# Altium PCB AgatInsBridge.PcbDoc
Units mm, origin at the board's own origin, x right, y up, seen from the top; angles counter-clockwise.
Board outline 85 x 24.01 mm, 2 copper layers (Top Layer, Bottom Layer); 85 components, 54 nets, 150 pads, 49 vias.
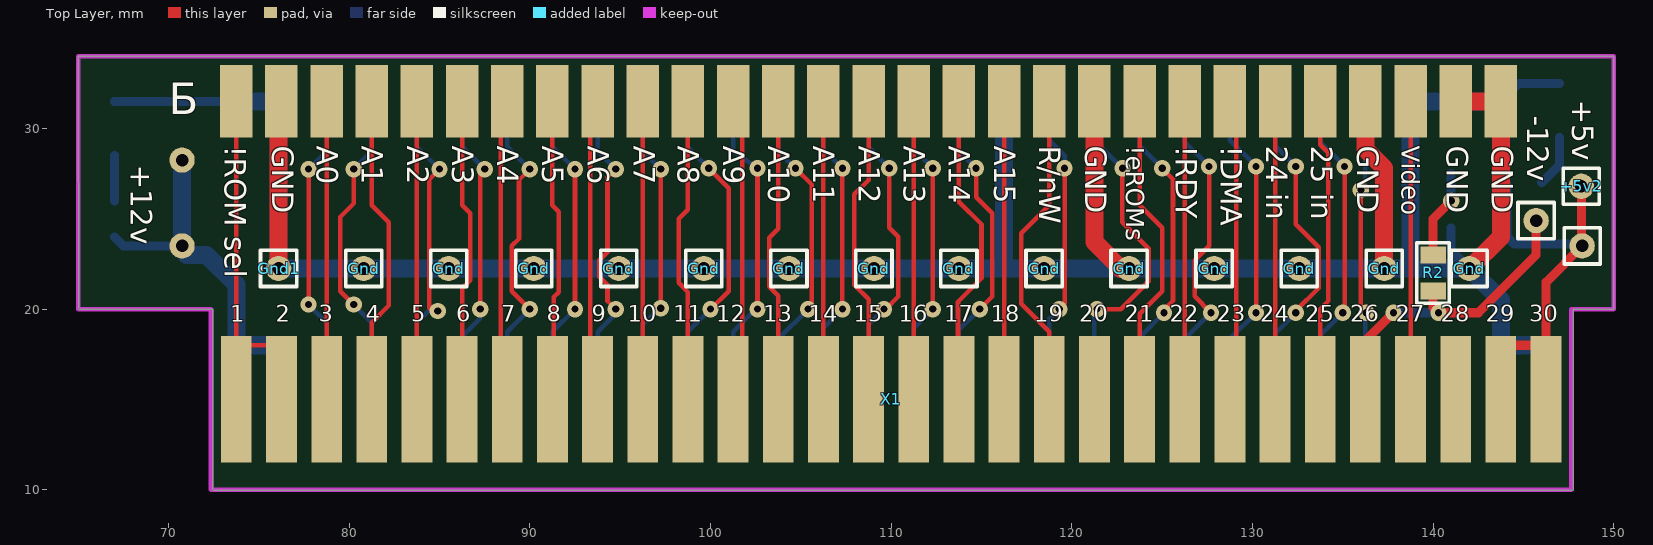
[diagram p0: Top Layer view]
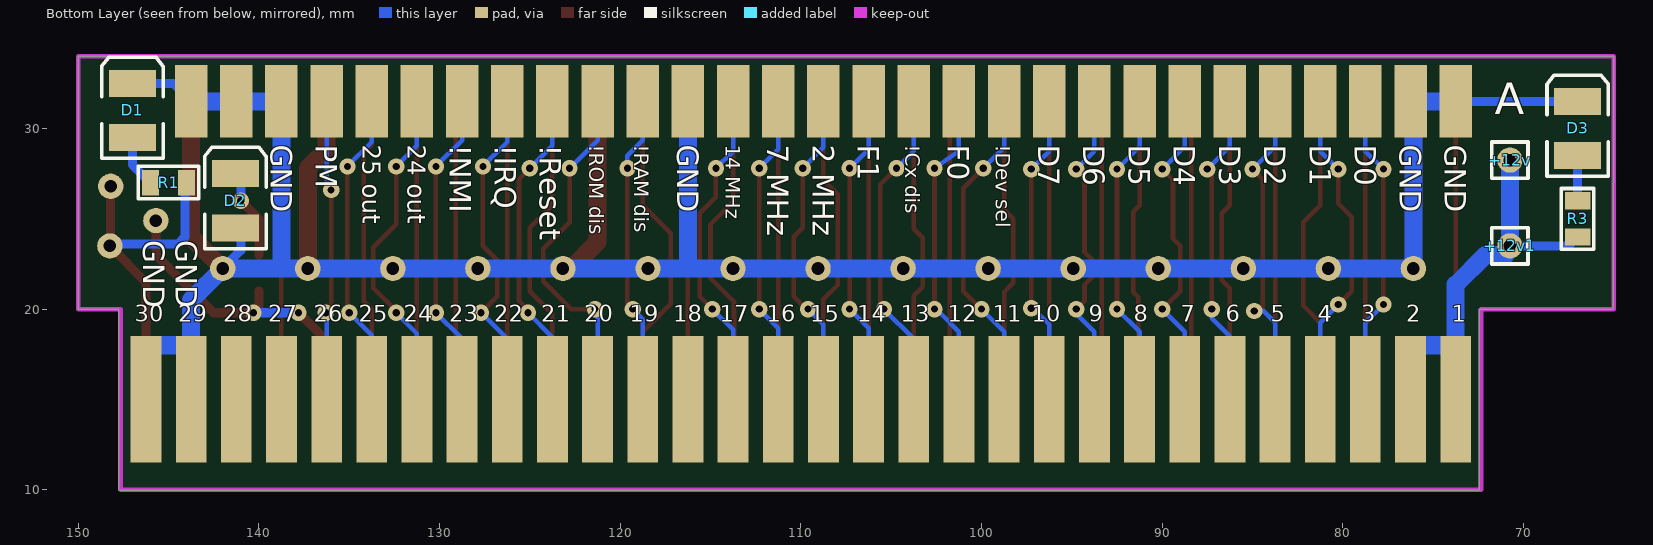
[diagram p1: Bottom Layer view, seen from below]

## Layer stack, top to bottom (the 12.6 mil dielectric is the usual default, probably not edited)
Top Solder: solder mask 0.0102, Solder Resist, Dk 3.5
Top Layer: signal copper 0.0356
Dielectric 1: dielectric 0.32, FR-4, Dk 4.8
Bottom Layer: signal copper 0.0356
Bottom Solder: solder mask 0.0102, Solder Resist, Dk 3.5

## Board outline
65.024,20 72.459,20 72.459,9.986 147.759,9.986 147.759,20 150,20 150,34 65,34

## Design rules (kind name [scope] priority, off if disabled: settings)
Clearance [All] p1: gap=0.254
PolygonConnect [All] p1: connectstyle=Relief reliefconductorwidth=0.254 reliefentries=4 polygonreliefangle="90 Angle" airgapwidth=0.254
RoutingVias [All] p1: holewidth=0.4 width=0.9 viastyle="Through Hole" minholewidth=0.4 minwidth=0.9 maxholewidth=0.4 maxwidth=0.9
SolderMaskExpansion [All] p1: expansion=0.102
Width [All] p1: maxlimit=1 minlimit=0.254 preferedwidth=0.5
30 further rules are at their usual default settings.

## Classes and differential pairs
component class AgatInsBridge: "2 MHz" "7 MHz" "14 MHz" "24 in" "24 out" "25 in" "25 out" "!Cx dis" "!Dev sel" !DMA !eROMs !IRQ !NMI "!RAM dis" !RDY !Reset "!ROM dis" "!ROM sel" +5v +5v2 +12v +12v1 +12v2 -12v A0 A1 A2 A3 A4 A5 A6 A7 A8 A9 A10 A11 A12 A13 A14 A15 D0 D1 D2 D3 D4 D5 D6 D7 F0 F1 Gnd GND PM R1 R2 R3 R/nW Video X1

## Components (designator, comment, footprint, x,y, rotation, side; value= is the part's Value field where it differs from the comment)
"2 MHz" "Wire pad" "Wire/Stick pad" 108.75,31.5 r180 bottom
"7 MHz" "Wire pad" "Wire/Stick pad" 111.25,31.5 r180 bottom
"14 MHz" "Wire pad" "Wire/Stick pad" 113.75,31.5 r180 bottom
"24 in" "Wire pad" "Wire/Stick pad" 131.25,31.5 r0 top
"24 out" "Wire pad" "Wire/Stick pad" 131.25,31.5 r180 bottom
"25 in" "Wire pad" "Wire/Stick pad" 133.75,31.5 r0 top
"25 out" "Wire pad" "Wire/Stick pad" 133.75,31.5 r180 bottom
"!Cx dis" "Wire pad" "Wire/Stick pad" 103.75,31.5 r180 bottom (schematic designator "!Cxxx dis")
"!Dev sel" "Wire pad" "Wire/Stick pad" 98.75,31.5 r180 bottom
!DMA "Wire pad" "Wire/Stick pad" 128.75,31.5 r0 top
!eROMs "Wire pad" "Wire/Stick pad" 123.75,31.5 r0 top (schematic designator "!eROM sel")
!IRQ "Wire pad" "Wire/Stick pad" 126.25,31.5 r180 bottom
!NMI "Wire pad" "Wire/Stick pad" 128.75,31.5 r180 bottom
"!RAM dis" "Wire pad" "Wire/Stick pad" 118.75,31.5 r180 bottom
!RDY "Wire pad" "Wire/Stick pad" 126.25,31.5 r0 top
!Reset "Wire pad" "Wire/Stick pad" 123.75,31.5 r180 bottom
"!ROM dis" "Wire pad" "Wire/Stick pad" 121.25,31.5 r180 bottom
"!ROM sel" "Wire pad" "Wire/Stick pad" 73.75,31.5 r0 top
+5v "Wire hole" "Wire hole" 148.25,23.5 r0 top (schematic designator +5v1)
+5v2 "Wire hole" "Wire hole" 148.2,26.8 r0 top
+12v "Wire hole" "Wire hole" 70.75,28.25 r180 bottom (schematic designator +12v2)
+12v1 "Wire hole" "Wire hole" 70.75,23.5 r180 bottom
-12v "Wire hole" "Wire hole" 145.7,24.9 r0 top
A0 "Wire pad" "Wire/Stick pad" 78.75,31.5 r0 top
A1 "Wire pad" "Wire/Stick pad" 81.25,31.5 r0 top
A2 "Wire pad" "Wire/Stick pad" 83.75,31.5 r0 top
A3 "Wire pad" "Wire/Stick pad" 86.25,31.5 r0 top
A4 "Wire pad" "Wire/Stick pad" 88.75,31.5 r0 top
A5 "Wire pad" "Wire/Stick pad" 91.25,31.5 r0 top
A6 "Wire pad" "Wire/Stick pad" 93.75,31.5 r0 top
A7 "Wire pad" "Wire/Stick pad" 96.25,31.5 r180 top
A8 "Wire pad" "Wire/Stick pad" 98.75,31.5 r0 top
A9 "Wire pad" "Wire/Stick pad" 101.25,31.5 r0 top
A10 "Wire pad" "Wire/Stick pad" 103.75,31.5 r0 top
A11 "Wire pad" "Wire/Stick pad" 106.25,31.5 r0 top
A12 "Wire pad" "Wire/Stick pad" 108.75,31.5 r0 top
A13 "Wire pad" "Wire/Stick pad" 111.25,31.5 r0 top
A14 "Wire pad" "Wire/Stick pad" 113.75,31.5 r0 top
A15 "Wire pad" "Wire/Stick pad" 116.25,31.5 r0 top
D0 "Wire pad" "Wire/Stick pad" 78.75,31.5 r180 bottom
D1 "Wire pad" "Wire/Stick pad" 81.25,31.5 r180 bottom
D1 "LED3" 3.5X2.8X1.9 147,31 r90 bottom
D2 "Wire pad" "Wire/Stick pad" 83.75,31.5 r180 bottom
D2 "LED3" 3.5X2.8X1.9 141.3,26 r90 bottom
D3 "Wire pad" "Wire/Stick pad" 86.25,31.5 r180 bottom
D3 "LED3" 3.5X2.8X1.9 67,30 r90 bottom
D4 "Wire pad" "Wire/Stick pad" 88.75,31.5 r180 bottom
D5 "Wire pad" "Wire/Stick pad" 91.25,31.5 r180 bottom
D6 "Wire pad" "Wire/Stick pad" 93.75,31.5 r180 bottom
D7 "Wire pad" "Wire/Stick pad" 96.25,31.5 r180 bottom
F0 "Wire pad" "Wire/Stick pad" 101.25,31.5 r180 bottom
F1 "Wire pad" "Wire/Stick pad" 106.25,31.5 r180 bottom
Gnd "Wire hole" "Wire hole" 85.508,22.25 r0 top
Gnd "Wire hole" "Wire hole" 94.923,22.25 r0 top
Gnd "Wire hole" "Wire hole" 104.338,22.25 r0 top
Gnd "Wire hole" "Wire hole" 113.754,22.25 r0 top
Gnd "Wire hole" "Wire hole" 123.169,22.25 r0 top
Gnd "Wire hole" "Wire hole" 132.585,22.25 r0 top
Gnd "Wire hole" "Wire hole" 142,22.25 r0 top
Gnd "Wire hole" "Wire hole" 80.8,22.25 r0 top
Gnd "Wire hole" "Wire hole" 90.215,22.25 r0 top
Gnd "Wire hole" "Wire hole" 99.631,22.25 r0 top
Gnd "Wire hole" "Wire hole" 109.046,22.25 r0 top
Gnd "Wire hole" "Wire hole" 118.461,22.25 r0 top
Gnd "Wire hole" "Wire hole" 127.877,22.25 r0 top
Gnd "Wire hole" "Wire hole" 137.292,22.25 r0 top
GND "Wire pad" "Wire/Stick pad" 138.75,31.5 r180 bottom
GND "Wire pad" "Wire/Stick pad" 116.25,31.5 r180 bottom
GND "Wire pad" "Wire/Stick pad" 121.25,31.5 r0 top
GND "Wire pad" "Wire/Stick pad" 141.25,31.5 r0 top
GND "Wire pad" "Wire/Stick pad" 143.75,31.5 r0 top
GND "Wire pad" "Wire/Stick pad" 76.25,31.5 r0 top
GND "Wire pad" "Wire/Stick pad" 76.25,31.5 r180 bottom
GND "Wire pad" "Wire/Stick pad" 73.75,31.5 r180 bottom
GND "Wire pad" "Wire/Stick pad" 141.25,31.5 r180 bottom
GND "Wire pad" "Wire/Stick pad" 143.75,31.5 r180 bottom
GND "Wire pad" "Wire/Stick pad" 136.25,31.5 r0 top
Gnd1 "Wire hole" "Wire hole" 76.093,22.25 r0 top (schematic designator Gnd)
PM "Wire pad" "Wire/Stick pad" 136.25,31.5 r180 bottom (schematic designator ПМ)
R1 "Res3" r0805 145,27 r180 bottom
R2 "Res3" r0805 140,22 r270 top
R3 "Res3" r0805 67,25 r270 bottom
R/nW "Wire pad" "Wire/Stick pad" 118.75,31.5 r0 top
Video "Wire pad" "Wire/Stick pad" 138.75,31.5 r0 top
X1 "AGAT_CON" AGAT_CONP 110,15 r0 top locked

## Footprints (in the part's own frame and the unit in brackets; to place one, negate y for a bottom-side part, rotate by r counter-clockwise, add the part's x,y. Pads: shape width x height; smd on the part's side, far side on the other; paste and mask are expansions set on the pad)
3.5X2.8X1.9 [mm] "SM LED; 2 C-Bend Leads; Body 3.5 x 2.8 x 1.9 mm, inc leads (LxWxH typ)"
  rect 1.5x2.6 smd: 1(-1.5,0) 2(1.5,0)
  silkscreen extent -2.65,-1.7 2.95,1.7
AGAT_CONP [mm]
  rect 1.7x7 smd far side: A1(-36.25,0) A2(-33.75,0) A3(-31.25,0) A4(-28.75,0) A5(-26.25,0) A6(-23.75,0) A7(-21.25,0) A8(-18.75,0) A9(-16.25,0) A10(-13.75,0) A11(-11.25,0) A12(-8.75,0) A13(-6.25,0) A14(-3.75,0) A15(-1.25,0) A16(1.25,0) A17(3.75,0) A18(6.25,0) A19(8.75,0) A20(11.25,0) A21(13.75,0) A22(16.25,0) A23(18.75,0) A24(21.25,0) A25(23.75,0) A26(26.25,0) A27(28.75,0) A28(31.25,0) A29(33.75,0) A30(36.25,0)
  rect 1.7x7 smd: B1(-36.25,0) B2(-33.75,0) B3(-31.25,0) B4(-28.75,0) B5(-26.25,0) B6(-23.75,0) B7(-21.25,0) B8(-18.75,0) B9(-16.25,0) B10(-13.75,0) B11(-11.25,0) B12(-8.75,0) B13(-6.25,0) B14(-3.75,0) B15(-1.25,0) B16(1.25,0) B17(3.75,0) B18(6.25,0) B19(8.75,0) B20(11.25,0) B21(13.75,0) B22(16.25,0) B23(18.75,0) B24(21.25,0) B25(23.75,0) B26(26.25,0) B27(28.75,0) B28(31.25,0) B29(33.75,0) B30(36.25,0)
  Keep-Out Layer lines w0.254: -37.65,5 -37.65,-5 37.65,-5 37.65,5
r0805 [mm]
  rect 0.95x1.4 smd: 1(-1,0) 2(1,0)
  silkscreen extent -1.68,-0.9 1.68,0.9, body extent -1,-0.63 1,0.63, height 0.78
"Wire hole" [mm]
  round 1.4 hole 0.7: 0(0,0)
  silkscreen extent -1,-1 1,1
"Wire/Stick pad" [mm] "Для пайки угловых разъёмов"
  rect 1.8x4 smd: 0(0,0)

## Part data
D1 D2 D3: "Typical BLUE SiC LED"
R1 R2 R3: "Resistor"

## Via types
v1: diameter 0.9, hole 0.4, Top Layer to Bottom Layer, tented both sides, 49 vias

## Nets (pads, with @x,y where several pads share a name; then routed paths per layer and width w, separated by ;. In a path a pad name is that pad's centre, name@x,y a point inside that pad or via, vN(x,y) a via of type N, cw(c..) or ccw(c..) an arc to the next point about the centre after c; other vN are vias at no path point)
GND: D1.2 D2.1 D3.2 Gnd1.0 GND.0 Gnd.0 X1.A29 X1.A30 | length 162.9
  Top Layer w1: Gnd1.0@76.092,22.25 GND.0@76.092,30.15 ; GND.0@76.25,31.5 76.25,30.4 GND.0@76.5,30.15 ; GND.0@121.25,31.5 121.25,23.711 Gnd.0@122.735,22.226 ; GND.0@136.25,31.5 136.25,28.85 137.292,27.808 Gnd.0@137.292,22.25 ; GND.0@141.25,31.5 143.75,31.5 143.75,24 Gnd.0@142,22.25
  Bottom Layer w0.5: D3.2 GND.0@73.75,31.5 ; D2.1@141,24.5 141,23.25 Gnd.0@142,22.25 ; GND.0@143.75,31.5 144.75,32.5 D1.2
  Bottom Layer w1: GND.0@73.75,31.5 GND.0@76.092,31.5 ; Gnd1.0@76.092,22.25 GND.0@76.092,31.5 ; Gnd1.0@76.25,22.25 116.25,22.25 ; GND.0@76.25,31.5 GND.0@76.092,31.5 ; GND.0@116.25,31.5 116.25,22.25 ; 138.75,22.3 138.75,31.5 141.25,31.5 GND.0@143.75,31.5 ; X1.A30@146.25,18 143.75,18 143.75,20.5 142,22.25 137.292,22.25 132.585,22.25 127.877,22.25 123.169,22.25 118.461,22.25 116.25,22.25
"Net2 MHz_0": "2 MHz.0" X1.A15 | length 17.9
  Top Layer w0.254: v1(109.6,20) 109.7,20 110.4,20.7 110.4,24 109.9,24.5 v1(109.9,27.8)
  Bottom Layer w0.254: X1.A15 108.75,19.15 v1(109.6,20) ; 108.75,31.5 108.75,28.95 v1(109.9,27.8)
"Net7 MHz_0": "7 MHz.0" X1.A16 | length 17.4
  Top Layer w0.254: v1(112.3,20) v1(112.3,27.8)
  Bottom Layer w0.254: X1.A16 111.25,18.95 v1(112.3,20) ; 111.25,31.5 111.25,28.85 v1(112.3,27.8)
"Net14 MHz_0": "14 MHz.0" X1.A17 | length 18
  Top Layer w0.254: v1(114.7,27.8) 114.7,26.2 115.6,25.3 115.6,20.7 v1(114.9,20)
  Bottom Layer w0.254: X1.A17 113.75,18.85 v1(114.9,20) ; 113.75,31.5 113.75,28.75 v1(114.7,27.8)
"Net24 in_0": "24 in.0" X1.B24 | length 16.5
  Top Layer w0.254: X1.B24 131.25,19.25 131.25,31.5
"Net24 out_0": "24 out.0" X1.A24 | length 18.5
  Top Layer w0.254: v1(132.4,19.8) 132.4,19.903 133.666,21.169 133.666,23.434 132.4,24.7 v1(132.4,27.9)
  Bottom Layer w0.254: X1.A24 131.25,18.65 v1(132.4,19.8) ; 131.25,31.5 131.25,29.05 v1(132.4,27.9)
"Net25 in_0": "25 in.0" X1.B25 | length 16.9
  Top Layer w0.254: X1.B25 133.75,20 134.2,20.45 134.2,28.65 133.75,29.1 133.75,31.5
"Net25 out_0": "25 out.0" X1.A25 | length 17.6
  Top Layer w0.254: v1(135,19.8) 135.1,19.9 v1(135.1,27.9)
  Bottom Layer w0.254: X1.A25 133.75,18.55 v1(135,19.8) ; 133.75,31.5 133.75,29.25 v1(135.1,27.9)
"Net!Cxxx dis_0": "!Cx dis.0" X1.A13 | length 18
  Top Layer w0.254: v1(104.7,27.8) 105.6,26.9 105.6,20.2 v1(105.4,20)
  Bottom Layer w0.254: X1.A13 103.75,18.35 v1(105.4,20) ; 103.75,31.5 103.75,28.75 v1(104.7,27.8)
"Net!Dev sel_0": "!Dev sel.0" X1.A11 | length 18.4
  Top Layer w0.254: v1(99.9,27.8) 101,26.7 101,21 v1(100,20)
  Bottom Layer w0.254: X1.A11 98.75,18.75 v1(100,20) ; 98.75,31.5 98.75,28.95 v1(99.9,27.8)
Net!DMA_0: !DMA.0 X1.B23 | length 16.8
  Top Layer w0.254: X1.B23 129.1,15.35 129.1,31.15 !DMA.0
"Net!eROM sel_0": !eROMs.0 X1.B21 | length 17.5
  Top Layer w0.254: X1.B21 123.75,19.75 125,21 125,24.5 123.75,25.75 !eROMs.0
Net!IRQ_0: !IRQ.0 X1.A22 | length 18.4
  Top Layer w0.254: v1(127.6,27.9) 127.6,23.502 126.796,22.698 126.796,20.704 v1(127.7,19.8)
  Bottom Layer w0.254: X1.A22 126.25,18.35 v1(127.7,19.8) ; !IRQ.0 126.25,29.25 v1(127.6,27.9)
Net!NMI_0: !NMI.0 X1.A23 | length 17.7
  Top Layer w0.254: v1(130.2,19.8) v1(130.2,27.9)
  Bottom Layer w0.254: X1.A23 128.75,18.35 v1(130.2,19.8) ; !NMI.0 128.75,29.35 v1(130.2,27.9)
"Net!RAM dis_0": "!RAM dis.0" X1.A19 | length 17.3
  Top Layer w0.254: v1(119.3,20) 119.6,20.3 v1(119.6,27.8)
  Bottom Layer w0.254: X1.A19 118.75,19.45 v1(119.3,20) ; 118.75,31.5 118.75,29.35 119.6,28.5 v1(119.6,27.8) v1@119.5,27.9
Net!RDY_0: !RDY.0 X1.B22 | length 16.5
  Top Layer w0.254: X1.B22 !RDY.0
Net!Reset_0: !Reset.0 X1.A21 | length 18
  Top Layer w0.254: v1(125,27.8) 125.6,27.2 125.6,20.474 125.1,19.974 v1(125.1,19.8)
  Bottom Layer w0.254: X1.A21 123.75,18.45 v1(125.1,19.8) ; !Reset.0 123.75,29.05 v1(125,27.8)
"Net!ROM dis_0": "!ROM dis.0" X1.A20 | length 19.7
  Top Layer w0.254: v1(121.4,20) 122.7,20 124.25,21.55 124.25,23.35 122.8,24.8 v1(122.8,27.8)
  Bottom Layer w0.254: X1.A20 121.25,19.85 v1(121.4,20) ; 121.25,31.5 121.25,29.35 v1(122.8,27.8)
"Net!ROM sel_0": "!ROM sel.0" X1.B1 X1.B2 | length 19.5
  Top Layer w0.254: X1.B1 X1.B1@73.75,18 ; 73.75,31.5 X1.B1@73.75,18 ; X1.B2 X1.B2@76.25,15.5 ; X1.B2@76.25,18 X1.B1@73.75,18
Net+5v1_0: +5v2.0 +5v.0 R1.2 X1.B29 X1.B30 | length 22.7
  Top Layer w0.5: X1.B29@143.75,18 X1.B30@146.25,18 ; X1.B30 146.25,21.5 +5v.0 148.2,23.55 +5v2.0
  Bottom Layer w0.5: R1.2 144.099,26.901 144.099,24.001 144.5,23.6 148.15,23.6 +5v.0 ; +5v2.0@148.088,26.8 +5v2.0
Net+12v1_0: +12v1.0 +12v.0 R3.2 X1.A1 X1.A2 | length 21.3
  Bottom Layer w0.5: R3.2 67.5,23.5 +12v1.0
  Bottom Layer w1: +12v.0 +12v1.0 +12v1.0@71,23.25 ; +12v1.0@71,23 72.1,23 73.75,21.35 X1.A1 ; X1.A1@73.75,18 X1.A2@76.25,18
Net-12v_0: -12v.0 R2.2 X1.B26 | length 18
  Top Layer w0.5: X1.B26 136.25,18.25 v1(137.8,19.8) ; R2.2 140,20.1 v1(140.3,19.8) 142.5,19.8 145.7,23 -12v.0 -12v.0@145.8,25
  Bottom Layer w0.5: v1(137.8,19.8) v1(140.3,19.8)
NetA0_0: A0.0 X1.B3 | length 16.5
  Top Layer w0.254: X1.B3 A0.0
NetA1_0: A1.0 X1.B4 | length 17.3
  Top Layer w0.254: X1.B4 81.25,19.25 82.2,20.2 82.2,24.8 81.25,25.75 A1.0
NetA2_0: A2.0 X1.B5 | length 16.5
  Top Layer w0.254: X1.B5 A2.0
NetA3_0: A3.0 X1.B6 | length 16.9
  Top Layer w0.254: X1.B6 86.25,21.15 86.7,21.6 86.7,25.3 86.25,25.75 A3.0
NetA4_0: A4.0 X1.B7 | length 16.8
  Top Layer w0.254: X1.B7 88.392,15.358 88.392,31.142 A4.0
NetA5_0: A5.0 X1.B8 | length 16.8
  Top Layer w0.254: X1.B8 91.331,15.081 91.331,20.669 91.6,20.938 91.6,25.4 91.25,25.75 A5.0
NetA6_0: A6.0 X1.B9 | length 16.6
  Top Layer w0.254: X1.B9@93.45,15 93.334,15.116 93.334,31.384 A6.0@93.45,31.5
NetA7_0: A7.0 X1.B10 | length 16.5
  Top Layer w0.254: X1.B10 A7.0
NetA8_0: A8.0 X1.B11 | length 16.9
  Top Layer w0.254: X1.B11 98.75,20.95 98.25,21.45 98.25,25 98.75,25.5 A8.0
NetA9_0: A9.0 X1.B12 | length 16.5
  Top Layer w0.254: X1.B12@101.75,15 A9.0@101.75,31.5
NetA10_0: A10.0 X1.B13 | length 16.9
  Top Layer w0.254: X1.B13 103.75,20.75 103.257,21.243 103.257,23.957 103.75,24.45 A10.0
NetA11_0: A11.0 X1.B14 | length 16.5
  Top Layer w0.254: X1.B14 A11.0
NetA12_0: A12.0 X1.B15 | length 17.2
  Top Layer w0.254: X1.B15 108.75,20.55 107.965,21.335 107.965,26.365 108.75,27.15 A12.0
NetA13_0: A13.0 X1.B16 | length 16.5
  Top Layer w0.254: X1.B16 A13.0
NetA14_0: A14.0 X1.B17 | length 17.6
  Top Layer w0.254: X1.B17 113.7,15.05 113.7,20.4 115,21.7 115,24.7 113.75,25.95 A14.0
NetA15_0: A15.0 X1.B18 | length 16.5
  Top Layer w0.254: X1.B18 A15.0
NetD0_0: D0.0 X1.A3 | length 17.3
  Top Layer w0.254: v1(77.75,20.25) v1(77.75,27.75)
  Bottom Layer w0.254: v1(77.75,20.25) 78.75,19.25 X1.A3 ; v1(77.75,27.75) 78.75,28.75 D0.0
NetD1_0: D1.0 X1.A4 | length 17.9
  Top Layer w0.254: v1(80.25,20.25) 79.5,21 79.5,25.1 80.25,25.85 v1(80.25,27.75)
  Bottom Layer w0.254: v1(80.25,20.25) 81.25,19.25 X1.A4 ; v1(80.25,27.75) 81.25,28.75 D1.0
NetD1_1: D1.1 R1.1 | length 2.9
  Bottom Layer w0.5: R1.1 147,28 D1.1
NetD2_0: D2.0 X1.A5 | length 18.4
  Top Layer w0.254: v1(84.9,19.9) 84.6,19.9 84.427,20.073 84.427,27.177 v1(85,27.75)
  Bottom Layer w0.254: X1.A5 83.75,19.25 84.4,19.9 v1(84.9,19.9) ; D2.0 83.75,29 v1(85,27.75)
NetD2_2: D2.2 R2.1 | length 4.9
  Top Layer w0.5: R2.1 140,25 v1(141,26)
  Bottom Layer w0.5: v1(141,26) D2.2@141,27.5
NetD3_0: D3.0 X1.A6 | length 17.5
  Top Layer w0.254: v1(87.25,20) 87.25,27.5 v1(87.5,27.75)
  Bottom Layer w0.254: X1.A6 86.25,18.5 87.25,19.5 v1(87.25,20) ; D3.0 86.25,29 v1(87.5,27.75)
NetD3_1: D3.1 R3.1 | length 2.5
  Bottom Layer w0.5: R3.1 D3.1
NetD4_0: D4.0 X1.A7 | length 18.6
  Top Layer w0.254: v1(90,27.75) 89.4,27.15 89.4,23.9 89,23.5 89,21 v1(90,20) v1@90.25,20
  Bottom Layer w0.254: X1.A7 88.75,18.75 89.25,19.25 v1(90,20) ; D4.0 88.75,29 v1(90,27.75)
NetD5_0: D5.0 X1.A8 | length 17.5
  Top Layer w0.254: v1(92.5,20) v1(92.5,27.75)
  Bottom Layer w0.254: X1.A8 91.25,18.75 v1(92.5,20) ; D5.0 91.25,29 v1(92.5,27.75)
NetD6_0: D6.0 X1.A9 | length 18.1
  Top Layer w0.254: v1(94.75,20) 94.3,20.45 94.3,21.344 93.842,21.802 93.842,22.698 94.3,23.156 94.3,27.3 v1(94.75,27.75)
  Bottom Layer w0.254: X1.A9 93.75,18.75 94.75,19.75 v1(94.75,20) ; D6.0 93.75,28.75 v1(94.75,27.75)
NetD7_0: D7.0 X1.A10 | length 17.5
  Top Layer w0.254: v1@97.2,20 v1(97.25,20.05) v1(97.25,27.75)
  Bottom Layer w0.254: X1.A10 96.25,19.15 97.15,20.05 v1(97.25,20.05) ; D7.0 96.25,28.75 v1(97.25,27.75)
NetF0_0: F0.0 X1.A12 | length 17.8
  Top Layer w0.254: v1(102.6,20) v1(102.6,27.8)
  Bottom Layer w0.254: X1.A12 101.25,18.75 102.2,19.7 v1(102.6,20) ; F0.0 101.25,28.75 v1(102.6,27.8)
NetF1_0: F1.0 X1.A14 | length 17.4
  Top Layer w0.254: v1(107.3,20) v1(107.3,27.8)
  Bottom Layer w0.254: X1.A14 106.25,18.95 v1(107.3,20) ; F1.0 106.25,28.85 v1(107.3,27.8)
NetR/nW_0: R/nW.0 X1.B19 | length 17.8
  Top Layer w0.254: X1.B19 118.75,18.75 117.2,20.3 117.2,24.2 118.75,25.75 R/nW.0
NetVideo_0: Video.0 X1.B27 | length 16.5
  Top Layer w0.254: X1.B27 138.75,19.75 Video.0
NetX1_A26: PM.0 X1.A26 | length 16.7
  Top Layer w0.254: v1(136,26.6) 136,20.1 v1(136.3,19.8)
  Bottom Layer w0.254: v1(136,26.6) 136,26.7 136.25,26.95 PM.0 ; X1.A26 136.25,19.75 v1(136.3,19.8)
pads on no net: X1.A18 X1.A27 X1.A28 X1.B20 X1.B28

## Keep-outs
Keep-Out Layer:
  lines w0.254: 65,20 65,34 150,34 150,20 147.65,20 ; 65,20.024 65.024,20 72.35,20

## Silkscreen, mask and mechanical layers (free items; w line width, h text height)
Top Overlay:
  text "Б" at 70,30.2 h3
Bottom Overlay:
  text "А" at 71.6,30.2 h3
